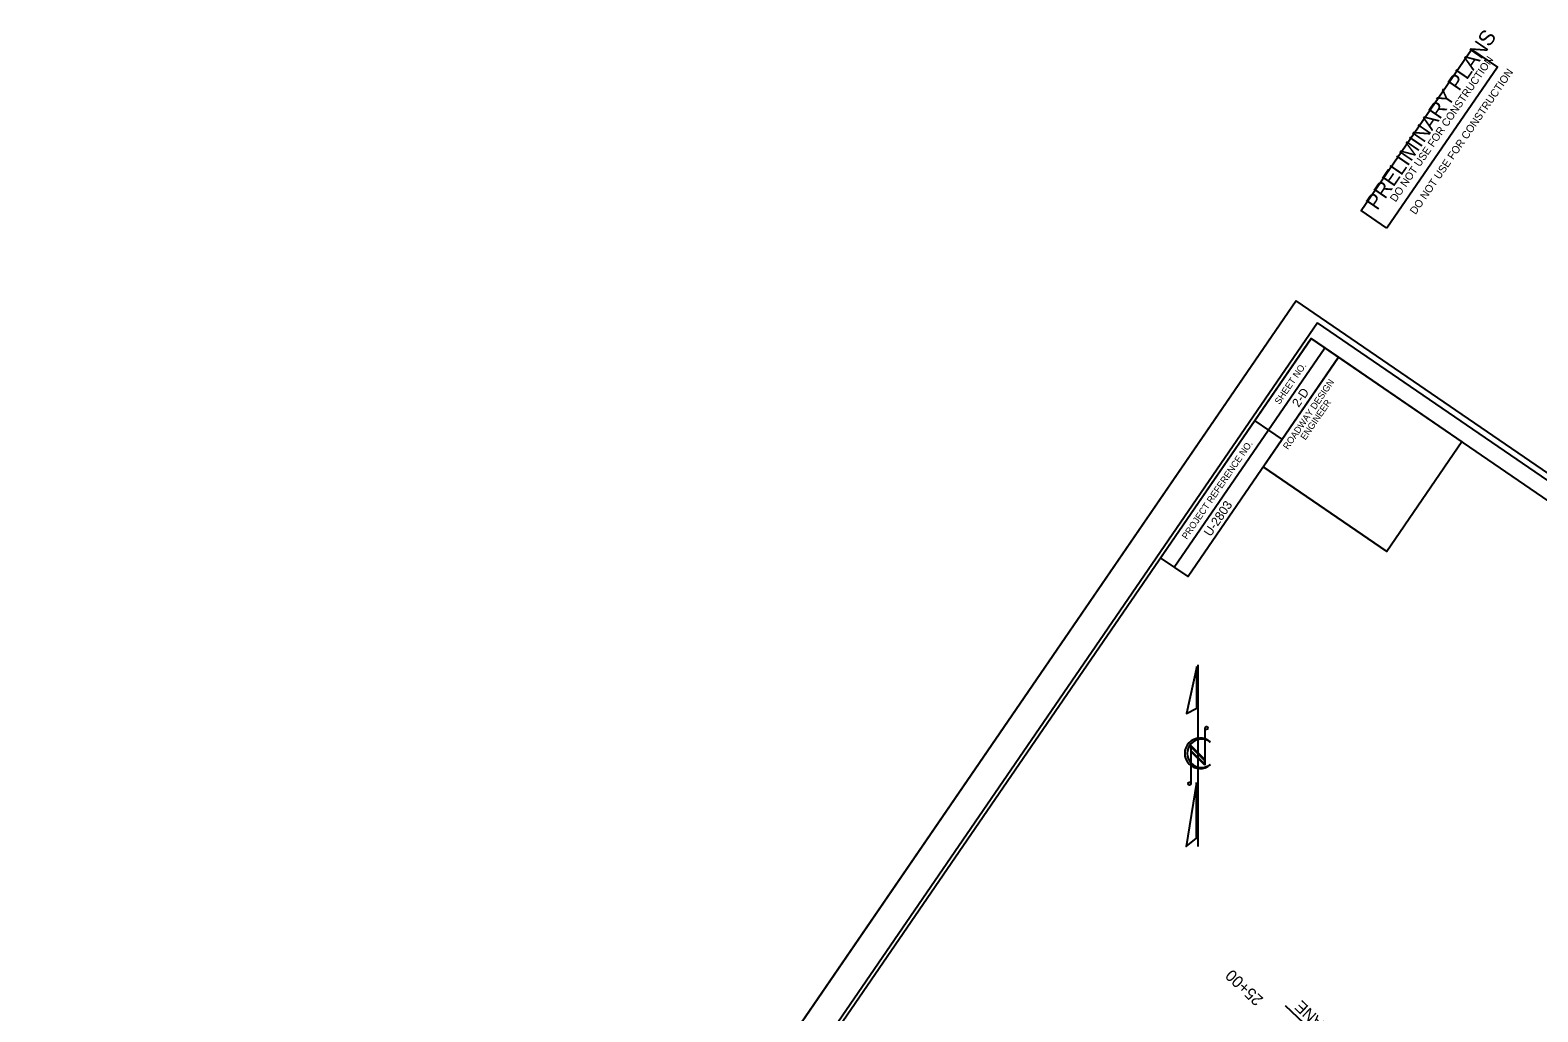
# Model space of a CAD drawing. Extents: x 1975573 to 1977432, y 778300 to 780514.
# Drawn here: x 1975573 to 1976706, y 779776 to 780514 of the extents above; entities that cross this region are included whole.
import ezdxf

# ---------------------------------------------------------------- set-up
doc = ezdxf.new("R2010")
doc.units = 0
for name, color, linetype in [('Prop Dimension Text', 7, 'Continuous'), ('Prop Horizontal Alignment Station Label', 7, 'Continuous'), ('Sheet Cutting Line CELL', 7, 'Continuous'), ('Sheet Data Field CELL', 7, 'Continuous'), ('Sheet North Arrow CELL', 7, 'Continuous'), ('Sheet Plot Border Inside CELL', 7, 'Continuous'), ('Sheet Plot Border Outside CELL', 7, 'Continuous'), ('Sheet Sticker Preliminary CELL', 7, 'Continuous'), ('Sheet Typical CELL', 7, 'Continuous')]:
    doc.layers.add(name, color=color, linetype=linetype)

msp = doc.modelspace()

# ---------------------------------------------------------------- linework, layer by layer
at = {"layer": 'Prop Dimension Text'}
msp.add_line((1976516.3, 779780.8), (1976562.2, 779737.3), dxfattribs=at)
at = {"layer": 'Sheet Cutting Line CELL'}
msp.add_line((1976524.6, 780310.7), (1975572.8, 778921.5), dxfattribs=at)
at = {"layer": 'Sheet North Arrow CELL'}
for p, q in [((1976450.7, 779900.4), (1976450.7, 780036.9)), ((1976455.8, 779989.4), (1976455.8, 779961.4)), ((1976459.7, 779979), (1976459.9, 779978.9)), ((1976455.8, 779965.8), (1976445.4, 779976.2)), ((1976445.4, 779976.2), (1976445.4, 779947.8)), ((1976455.8, 779964.8), (1976445.4, 779975.2)), ((1976445.4, 779975.2), (1976445.4, 779972.6)), ((1976455.8, 779962.2), (1976445.4, 779972.6)), ((1976445.4, 779972.6), (1976455.8, 779962.2)), ((1976455.8, 779961.4), (1976445.4, 779971.9)), ((1976455.8, 779962.2), (1976455.8, 779964.8))]:
    msp.add_line(p, q, dxfattribs=at)
for points in [[(1976449.8, 780035.8), (1976442, 780000.3), (1976449.8, 780004.3)], [(1976449.6, 779948.5), (1976441.9, 779900.4), (1976449.6, 779906.5)]]:
    msp.add_lwpolyline(points, close=True, dxfattribs=at)
for centre in [(1976457, 779989.4), (1976444.3, 779947.7)]:
    msp.add_circle(centre, 1.11, dxfattribs=at)
for centre, radius, start, end in [((1976452.2, 779970.4), 11.5, 47.84, 312.3941), ((1976453.3, 779970.4), 10.7, 53.095, 308.6287)]:
    msp.add_arc(centre, radius, start, end, dxfattribs=at)
at = {"layer": 'Sheet Plot Border Inside CELL'}
msp.add_lwpolyline([(1976540.6, 780294.3), (1975598.6, 778919.5), (1976469, 778323.1), (1977411, 779697.9)], close=True, dxfattribs=at)
at = {"layer": 'Sheet Plot Border Outside CELL'}
msp.add_lwpolyline([(1976524.6, 780310.7), (1975572.8, 778921.5), (1976480.2, 778299.7), (1977432.1, 779688.9)], close=True, dxfattribs=at)
at = {"layer": 'Sheet Sticker Preliminary CELL'}
msp.add_lwpolyline([(1976592.7, 780365.4), (1976573.3, 780378.7), (1976656.4, 780499.9), (1976675.8, 780486.6)], close=True, dxfattribs=at)
at = {"layer": 'Sheet Typical CELL'}
for p, q in [((1976432.9, 780110.4), (1976546, 780275.4)), ((1976493.3, 780220.6), (1976513.9, 780206.5)), ((1976499.8, 780185.9), (1976592.6, 780122.3))]:
    msp.add_line(p, q, dxfattribs=at)
for points in [[(1976535.7, 780282.5), (1975687.8, 779045.1), (1976554, 778451.6), (1977401.8, 779689)], [(1976422.6, 780117.5), (1976535.7, 780282.5), (1976556.3, 780268.4), (1976443.2, 780103.3)], [(1976499.8, 780185.9), (1976556.3, 780268.4), (1976649.1, 780204.8), (1976592.6, 780122.3)]]:
    msp.add_lwpolyline(points, close=True, dxfattribs=at)

# ---------------------------------------------------------------- texts
at = {"layer": 'Prop Dimension Text'}
msp.add_text('LANE', height=8.75, rotation=136.4577, dxfattribs=at).set_placement((1976550.8, 779764.1))
at = {"layer": 'Prop Horizontal Alignment Station Label'}
msp.add_text('25+00', height=8.75, rotation=136.6823, dxfattribs=at).set_placement((1976500.3, 779786))
at = {"layer": 'Sheet Data Field CELL'}
for s, p in [('2-D', (1976526.4, 780230.2)), (' U-2803  ', (1976458.7, 780130.9))]:
    msp.add_text(s, height=6.75, rotation=55.5805, dxfattribs=at).set_placement(p)
at = {"layer": 'Sheet Sticker Preliminary CELL'}
for s, height, p in [('PRELIMINARY PLANS', 11.52, (1976585.5, 780378.2)), ('DO NOT USE FOR CONSTRUCTION', 5.76, (1976599.3, 780384.6)), ('DO NOT USE FOR CONSTRUCTION', 5.76, (1976614.2, 780375.2))]:
    msp.add_text(s, height=height, rotation=55.5805, dxfattribs=at).set_placement(p)
at = {"layer": 'Sheet Typical CELL'}
for s, p in [('SHEET NO.', (1976512, 780232.4)), ('ROADWAY DESIGN', (1976518.3, 780198.5)), ('ENGINEER', (1976531.4, 780205.6)), ('PROJECT REFERENCE NO.', (1976442.3, 780130.9))]:
    msp.add_text(s, height=5, rotation=55.5805, dxfattribs=at).set_placement(p)

doc.saveas('drawing.dxf')
